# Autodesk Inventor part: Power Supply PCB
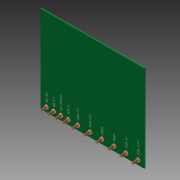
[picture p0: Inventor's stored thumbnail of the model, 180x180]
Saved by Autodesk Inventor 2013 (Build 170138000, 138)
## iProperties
Company: Autodesk Inc.
Created: 2006-09
Part Number: Power Supply PCB
Document SubType Name: Modeling
Designer: Autodesk Inc.
Density: 1 g/cm^3
Mass: 25.5291 g
Surface Area: 329.975 cm^2
Volume: 25.5291 cm^3
Material: Allgemein
Author: Autodesk Inc.
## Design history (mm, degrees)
sketch "Sketch1"
  geometry: L1 (-70.627, 69.974)-(65.898, 69.974); L2 (65.898, 69.974)-(65.898, -44.326); L3 (65.898, -44.326)-(-70.627, -44.326); L4 (-70.627, -44.326)-(-70.627, 69.974); C1 r 2.54 at (58.278, -37.976); C2 r 2.54 at (42.403, -37.976); C3 r 2.54 at (26.528, -37.976); C4 r 2.54 at (10.653, -37.976); C5 r 2.54 at (-5.222, -37.976); C6 r 2.54 at (-21.097, -37.976); C7 r 2.54 at (-33.797, -37.976); C8 r 2.54 at (-43.322, -37.976); C9 r 2.54 at (-62.372, -37.976); C10 r 2.54 at (-52.847, -37.976); C11 r 1.422 at (-62.372, -37.976); C12 r 1.422 at (-52.847, -37.976); C13 r 1.422 at (-43.322, -37.976); C14 r 1.422 at (-33.797, -37.976); C15 r 1.422 at (-21.097, -37.976); C16 r 1.422 at (-5.222, -37.976); C17 r 1.422 at (10.653, -37.976); C18 r 1.422 at (26.528, -37.976); C19 r 1.422 at (42.403, -37.976); C20 r 1.422 at (58.278, -37.976)
  constraints: 20 centre point, 18 equal radius, 10 coincident, 9 horizontal alignment, 8 end point, 2 parallel, 1 horizontal, 1 perpendicular
  dimensions: "d0" = 5.08 diameter of C10; "d1" = 6.35 distance from line of L3 C5.centre; "d2" = 7.62 distance from line of L2 C1.centre; "d3" = 136.525 distance of L2.end L3.end; "d4" = 114.3 distance of L1.end L2.end; "d5" = 15.875 distance of C2.centre C1.centre; "d6" = 15.875 distance of C3.centre C2.centre; "d7" = 15.875 distance of C4.centre C3.centre; "d8" = 15.875 distance of C5.centre C4.centre; "d9" = 15.875 distance of C6.centre C5.centre; "d10" = 12.7 distance of C7.centre C6.centre; "d11" = 9.525 distance of C8.centre C7.centre; "d12" = 9.525 distance of C10.centre C8.centre; "d13" = 9.525 distance of C9.centre C10.centre; "d14" = 2.8448 diameter of C11
extrude "Extrusion1" new body sketch "Sketch1" distance "d15" = 1.5875; taper "d16" = 0 deg
extrude "Extrusion2" join sketch "Sketch1" distance "d17" = 3.175; taper "d18" = 0 deg
extrude "Extrusion3" join sketch "Sketch1" distance "d19" = 9.525; taper "d20" = 0 deg
thread "Thread1" dims "d21" = 25.4, "d22" = 0
thread "Thread2" dims "d23" = 25.4, "d24" = 0
thread "Thread3" dims "d25" = 25.4, "d26" = 0
thread "Thread4" dims "d27" = 25.4, "d28" = 0
thread "Thread5" dims "d29" = 25.4, "d30" = 0
thread "Thread6" dims "d31" = 25.4, "d32" = 0
thread "Thread7" dims "d33" = 25.4, "d34" = 0
thread "Thread8" dims "d35" = 25.4, "d36" = 0
thread "Thread9" dims "d37" = 25.4, "d38" = 0
thread "Thread10" dims "d39" = 25.4, "d40" = 0
sketch "Sketch2"
  geometry: L1 (65.898, 69.974)-(65.898, -44.326) reference; L2 (59.866, -14.978)-(59.866, -33.044); L3 (59.866, -33.044)-(56.69, -33.044); L4 (56.69, -33.044)-(56.69, -14.978); L5 (56.69, -14.978)-(59.866, -14.978); L6 (40.815, -14.978)-(43.991, -14.978); L7 (43.991, -14.978)-(43.991, -33.044); L8 (43.991, -33.044)-(40.815, -33.044); L9 (40.815, -33.044)-(40.815, -14.978); L10 (24.94, -14.978)-(28.116, -14.978); L11 (28.116, -14.978)-(28.116, -33.044); L12 (28.116, -33.044)-(24.94, -33.044); L13 (24.94, -33.044)-(24.94, -14.978); L14 (9.065, -14.978)-(12.241, -14.978); L15 (12.241, -14.978)-(12.241, -33.044); L16 (12.241, -33.044)-(9.065, -33.044); L17 (9.065, -33.044)-(9.065, -14.978); L18 (-6.81, -14.978)-(-3.634, -14.978); L19 (-3.634, -14.978)-(-3.634, -33.044); L20 (-3.634, -33.044)-(-6.81, -33.044); L21 (-6.81, -33.044)-(-6.81, -14.978); L22 (-63.96, -14.978)-(-60.784, -14.978); L23 (-60.784, -14.978)-(-60.784, -33.044); L24 (-60.784, -33.044)-(-63.96, -33.044); L25 (-63.96, -33.044)-(-63.96, -14.978); L26 (-54.435, -14.978)-(-51.259, -14.978); L27 (-51.259, -14.978)-(-51.259, -33.044); L28 (-51.259, -33.044)-(-54.435, -33.044); L29 (-54.435, -33.044)-(-54.435, -14.978); L30 (-44.91, -14.978)-(-41.734, -14.978); L31 (-41.734, -14.978)-(-41.734, -33.044); L32 (-41.734, -33.044)-(-44.91, -33.044); L33 (-44.91, -33.044)-(-44.91, -14.978); L34 (-35.385, -14.978)-(-32.209, -14.978); L35 (-32.209, -14.978)-(-32.209, -33.044); L36 (-32.209, -33.044)-(-35.385, -33.044); L37 (-35.385, -33.044)-(-35.385, -14.978); L38 (-22.685, -14.978)-(-19.509, -14.978); L39 (-19.509, -14.978)-(-19.509, -33.044); L40 (-19.509, -33.044)-(-22.685, -33.044); L41 (-22.685, -33.044)-(-22.685, -14.978); C1 r 2.54 at (-52.847, -37.976) reference; C2 r 2.54 at (-62.372, -37.976) reference; C3 r 2.54 at (-43.322, -37.976) reference; C4 r 2.54 at (-33.797, -37.976) reference; C5 r 2.54 at (-21.097, -37.976) reference; C6 r 2.54 at (-5.222, -37.976) reference; C7 r 2.54 at (10.653, -37.976) reference; C8 r 2.54 at (26.528, -37.976) reference; C9 r 2.54 at (42.403, -37.976) reference; C10 r 2.54 at (58.278, -37.976) reference; 10 further points
  constraints: 10 midpoint, 10 vertical alignment, 9 horizontal alignment, 1 parallel, 20 other
  dimensions: "d42" = 3.17644 distance of L2.end L3.end
emboss "Emboss1" sketch "Sketch2" dims "d16" = 0, "d43" = 0.254, "d44" = 0
body "Solid1"
